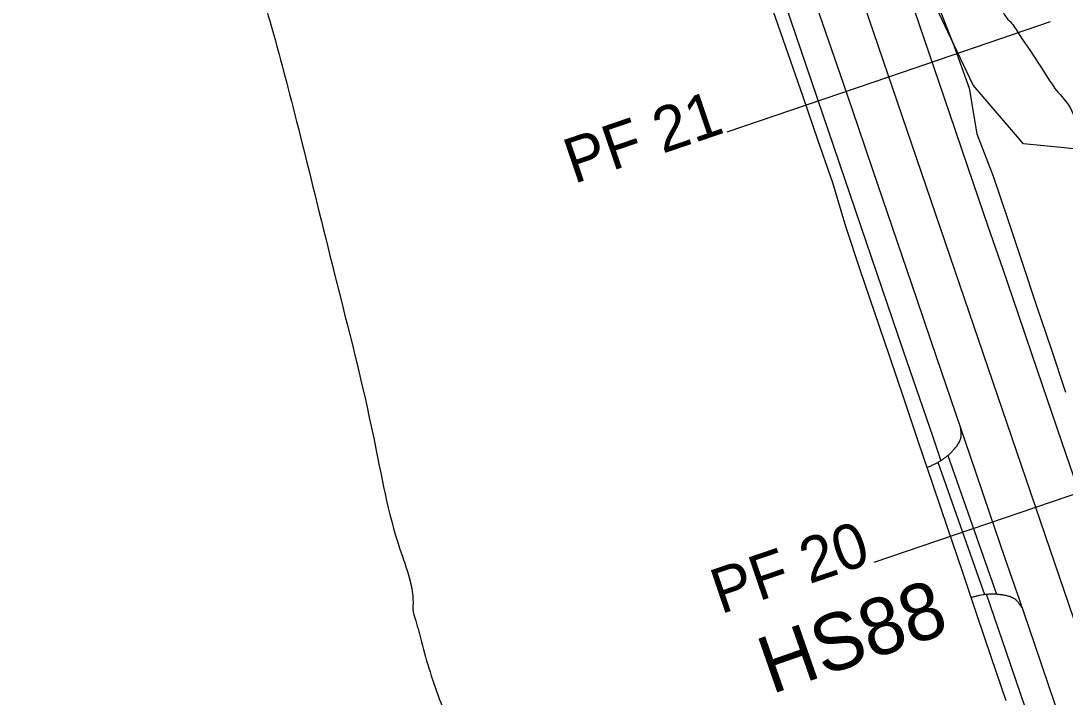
# Model space of a CAD drawing. Extents: x -478102 to -473059, y -1117705 to -1114104.
# Drawn here: x -476532.03 to -476486.18, y -1116879.78 to -1116850.07 of the extents above; entities that cross this region are included whole.
import ezdxf

# ---------------------------------------------------------------- set-up
doc = ezdxf.new("R2010")
doc.units = 0
for name, color, linetype in [('cesty', 7, 'Continuous'), ('POLYGONY_SITUACE_PF', 7, 'Continuous'), ('POLYGONY_SITUACE_PF_POPISY', 7, 'Continuous'), ('POLYGONY_SITUACE_PO', 7, 'Continuous'), ('popis', 7, 'Continuous'), ('RozhraniKultur', 7, 'Continuous'), ('TP_HS', 7, 'Continuous'), ('Vrstevnice_hlavni', 7, 'Continuous'), ('Vrstevnice_vedlejsi', 7, 'Continuous')]:
    doc.layers.add(name, color=color, linetype=linetype)

msp = doc.modelspace()

# ---------------------------------------------------------------- linework, layer by layer
at = {"layer": 'cesty'}
for p, q in [((-476498.334, -1116851.512), (-476498.997, -1116849.625)), ((-476498.334, -1116851.512), (-476498.997, -1116849.625)), ((-476497.785, -1116851.325), (-476498.43, -1116849.432)), ((-476492.79, -1116849.622), (-476491.499, -1116853.408)), ((-476497.68, -1116853.402), (-476498.334, -1116851.512)), ((-476497.68, -1116853.402), (-476498.334, -1116851.512)), ((-476495.849, -1116857.004), (-476497.785, -1116851.325)), ((-476497.031, -1116855.294), (-476497.68, -1116853.402)), ((-476497.031, -1116855.294), (-476497.68, -1116853.402)), ((-476491.499, -1116853.408), (-476490.208, -1116857.194)), ((-476496.382, -1116857.185), (-476497.031, -1116855.294)), ((-476496.382, -1116857.185), (-476497.031, -1116855.294)), ((-476493.268, -1116864.576), (-476495.849, -1116857.004)), ((-476495.805, -1116859.102), (-476496.382, -1116857.185)), ((-476495.805, -1116859.102), (-476496.382, -1116857.185)), ((-476490.208, -1116857.194), (-476489.563, -1116859.087)), ((-476495.173, -1116860.999), (-476495.805, -1116859.102)), ((-476495.173, -1116860.999), (-476495.805, -1116859.102)), ((-476489.563, -1116859.087), (-476488.918, -1116860.98)), ((-476494.532, -1116862.894), (-476495.173, -1116860.999)), ((-476494.532, -1116862.894), (-476495.173, -1116860.999)), ((-476488.918, -1116860.98), (-476488.272, -1116862.873)), ((-476493.891, -1116864.788), (-476494.532, -1116862.894)), ((-476493.891, -1116864.788), (-476494.532, -1116862.894)), ((-476488.272, -1116862.873), (-476487.627, -1116864.766)), ((-476493.251, -1116866.683), (-476493.891, -1116864.788)), ((-476493.251, -1116866.683), (-476493.891, -1116864.788)), ((-476491.977, -1116868.362), (-476493.268, -1116864.576)), ((-476487.627, -1116864.766), (-476486.982, -1116866.659)), ((-476486.982, -1116866.659), (-476486.336, -1116868.552)), ((-476492.61, -1116868.578), (-476493.251, -1116866.683)), ((-476492.61, -1116868.578), (-476493.251, -1116866.683)), ((-476491.636, -1116869.363), (-476491.977, -1116868.362)), ((-476491.969, -1116870.472), (-476492.61, -1116868.578)), ((-476491.969, -1116870.472), (-476492.61, -1116868.578)), ((-476486.336, -1116868.552), (-476485.046, -1116872.338)), ((-476491.328, -1116872.367), (-476491.969, -1116870.472)), ((-476491.328, -1116872.367), (-476491.969, -1116870.472)), ((-476490.687, -1116874.261), (-476491.328, -1116872.367)), ((-476490.687, -1116874.261), (-476491.328, -1116872.367)), ((-476490.046, -1116876.156), (-476490.687, -1116874.261)), ((-476490.046, -1116876.156), (-476490.687, -1116874.261)), ((-476488.751, -1116877.827), (-476489.625, -1116875.262)), ((-476489.406, -1116878.05), (-476490.046, -1116876.156)), ((-476489.406, -1116878.05), (-476490.046, -1116876.156)), ((-476488.765, -1116879.945), (-476489.406, -1116878.05)), ((-476488.765, -1116879.945), (-476489.406, -1116878.05)), ((-476487.46, -1116881.613), (-476488.751, -1116877.827))]:
    msp.add_line(p, q, dxfattribs=at)
for points in [[(-476497.221, -1116849.019), (-476495.93, -1116852.805)], [(-476491.797, -1116849.283), (-476491.061, -1116851.145)], [(-476491.061, -1116851.145), (-476490.394, -1116853.031)], [(-476495.93, -1116852.805), (-476495.285, -1116854.698)], [(-476490.394, -1116853.031), (-476490.058, -1116855.029)], [(-476495.285, -1116854.698), (-476494.64, -1116856.591)], [(-476490.058, -1116855.029), (-476489.332, -1116856.895)], [(-476494.64, -1116856.591), (-476493.994, -1116858.484)], [(-476489.332, -1116856.895), (-476488.696, -1116858.791)], [(-476493.994, -1116858.484), (-476493.349, -1116860.377)], [(-476488.696, -1116858.791), (-476488.061, -1116860.688)], [(-476493.349, -1116860.377), (-476492.704, -1116862.271)], [(-476488.061, -1116860.688), (-476487.426, -1116862.584)], [(-476492.704, -1116862.271), (-476492.058, -1116864.164)], [(-476487.426, -1116862.584), (-476486.79, -1116864.481)], [(-476492.058, -1116864.164), (-476491.413, -1116866.057)], [(-476486.79, -1116864.481), (-476486.155, -1116866.377)], [(-476491.413, -1116866.057), (-476490.768, -1116867.95)], [(-476490.768, -1116867.95), (-476490.122, -1116869.843)], [(-476490.122, -1116869.843), (-476489.477, -1116871.736)], [(-476489.477, -1116871.736), (-476488.832, -1116873.629)], [(-476488.832, -1116873.629), (-476488.186, -1116875.522)], [(-476488.186, -1116875.522), (-476487.541, -1116877.415)], [(-476487.541, -1116877.415), (-476486.896, -1116879.308)], [(-476486.896, -1116879.308), (-476486.25, -1116881.201)]]:
    msp.add_lwpolyline(points, dxfattribs=at)
at = {"layer": 'POLYGONY_SITUACE_PF'}
for points in [[(-476501.013, -1116854.94), (-476493.915, -1116852.52), (-476486.816, -1116850.1)], [(-476494.567, -1116873.851), (-476487.468, -1116871.431), (-476480.369, -1116869.011)]]:
    msp.add_lwpolyline(points, dxfattribs=at)
at = {"layer": 'POLYGONY_SITUACE_PO'}
msp.add_lwpolyline([(-476301.427, -1117045.065), (-476372.905, -1117052.019), (-476378.974, -1117051.908), (-476382.069, -1117051.436), (-476384.865, -1117050.444), (-476390.281, -1117047.7), (-476394.946, -1117043.817), (-476398.626, -1117038.989), (-476458.957, -1116938.029), (-476465.394, -1116926.586), (-476471.221, -1116914.82), (-476476.422, -1116902.765), (-476480.983, -1116890.454), (-476499.392, -1116836.452), (-476499.929, -1116834.228), (-476500.052, -1116831.944), (-476499.756, -1116829.676), (-476499.052, -1116827.5), (-476496.647, -1116821.88)], dxfattribs=at)
at = {"layer": 'RozhraniKultur'}
for p, q in [((-476488.011, -1116855.464), (-476490.21, -1116852.89)), ((-476485.323, -1116855.734), (-476488.011, -1116855.464))]:
    msp.add_line(p, q, dxfattribs=at)
msp.add_lwpolyline([(-476490.21, -1116852.89), (-476505.97, -1116819.69), (-476509.41, -1116806.69), (-476507.1, -1116784.61)], dxfattribs=at)
at = {"layer": 'TP_HS'}
for p, q in [((-476491.334, -1116869.169), (-476489.188, -1116875.25)), ((-476491.761, -1116869.463), (-476489.713, -1116875.267))]:
    msp.add_line(p, q, dxfattribs=at)
for points in [[(-476492.218, -1116869.684), (-476492.13, -1116869.645), (-476491.99, -1116869.579), (-476491.85, -1116869.51), (-476491.737, -1116869.45), (-476491.628, -1116869.383), (-476491.522, -1116869.312), (-476491.47, -1116869.274), (-476491.418, -1116869.236), (-476491.29, -1116869.131), (-476491.172, -1116869.018), (-476491.06, -1116868.897), (-476491.006, -1116868.834), (-476490.952, -1116868.769), (-476490.896, -1116868.696), (-476490.846, -1116868.62), (-476490.804, -1116868.539), (-476490.786, -1116868.497), (-476490.771, -1116868.452), (-476490.752, -1116868.384), (-476490.746, -1116868.349), (-476490.741, -1116868.314), (-476490.737, -1116868.245), (-476490.74, -1116868.176), (-476490.768, -1116867.95)], [(-476490.307, -1116875.396), (-476490.223, -1116875.374), (-476490.072, -1116875.337), (-476489.997, -1116875.32), (-476489.921, -1116875.303), (-476489.795, -1116875.279), (-476489.668, -1116875.262), (-476489.541, -1116875.251), (-476489.477, -1116875.248), (-476489.412, -1116875.245), (-476489.246, -1116875.247), (-476489.083, -1116875.26), (-476488.921, -1116875.284), (-476488.839, -1116875.299), (-476488.756, -1116875.316), (-476488.666, -1116875.338), (-476488.58, -1116875.366), (-476488.497, -1116875.402), (-476488.456, -1116875.424), (-476488.416, -1116875.449), (-476488.359, -1116875.49), (-476488.332, -1116875.513), (-476488.306, -1116875.537), (-476488.282, -1116875.562), (-476488.26, -1116875.588), (-476488.219, -1116875.644), (-476488.099, -1116875.838)]]:
    msp.add_spline(points, degree=3, dxfattribs=at)
at = {"layer": 'Vrstevnice_hlavni'}
msp.add_spline([(-476493.715, -1116836.779), (-476493.657, -1116837.782), (-476493.454, -1116838.814), (-476493.106, -1116839.874), (-476492.613, -1116840.964), (-476491.914, -1116842.563), (-476491.008, -1116844.672), (-476489.895, -1116847.291), (-476489.121, -1116849.068), (-476488.687, -1116850.006), (-476488.591, -1116850.102), (-476488.194, -1116850.666), (-476487.494, -1116851.699), (-476486.491, -1116853.199), (-476485.812, -1116854.196), (-476485.456, -1116854.691), (-476485.422, -1116854.683), (-476485.307, -1116854.78), (-476485.109, -1116854.984), (-476484.829, -1116855.293), (-476484.118, -1116857.163), (-476482.975, -1116860.594), (-476481.402, -1116865.585), (-476480.12, -1116869.665), (-476479.13, -1116872.833), (-476478.431, -1116875.088), (-476477.86, -1116876.887), (-476477.416, -1116878.229), (-476477.099, -1116879.115), (-476476.855, -1116880.078), (-476476.685, -1116881.12), (-476476.587, -1116882.239), (-476476.21, -1116884.112), (-476475.555, -1116886.737), (-476474.62, -1116890.115), (-476473.657, -1116893.01), (-476472.666, -1116895.422), (-476471.647, -1116897.352), (-476470.243, -1116900.412), (-476468.455, -1116904.603), (-476466.283, -1116909.925), (-476464.77, -1116913.634), (-476463.916, -1116915.731), (-476463.721, -1116916.214), (-476463.617, -1116916.722), (-476463.603, -1116917.256), (-476463.679, -1116917.815), (-476463.509, -1116918.911), (-476463.093, -1116920.547), (-476462.43, -1116922.72), (-476462.028, -1116926.548), (-476461.886, -1116932.03), (-476462.123, -1116946.304)], degree=3, dxfattribs=at)
at = {"layer": 'Vrstevnice_vedlejsi'}
msp.add_spline([(-476571.958, -1116704.162), (-476571.904, -1116704.215), (-476571.688, -1116704.429), (-476571.311, -1116704.803), (-476570.773, -1116705.338), (-476569.946, -1116706.363), (-476568.83, -1116707.879), (-476567.427, -1116709.886), (-476566.203, -1116711.628), (-476565.16, -1116713.105), (-476564.298, -1116714.317), (-476563.772, -1116715.225), (-476563.581, -1116715.829), (-476563.726, -1116716.129), (-476564.073, -1116716.669), (-476564.621, -1116717.45), (-476565.371, -1116718.471), (-476565.697, -1116719.715), (-476565.599, -1116721.18), (-476565.077, -1116722.867), (-476563.322, -1116725.926), (-476560.334, -1116730.356), (-476556.114, -1116736.158), (-476552.562, -1116741.631), (-476549.677, -1116746.776), (-476547.46, -1116751.593), (-476545.693, -1116756.042), (-476544.374, -1116760.122), (-476543.504, -1116763.833), (-476542.206, -1116769.314), (-476540.482, -1116776.566), (-476538.329, -1116785.587), (-476536.736, -1116792.746), (-476535.702, -1116798.044), (-476535.228, -1116801.481), (-476533.66, -1116807.541), (-476530.999, -1116816.224), (-476527.246, -1116827.53), (-476524.726, -1116835.32), (-476523.44, -1116839.595), (-476523.389, -1116840.354), (-476523.331, -1116841.083), (-476523.266, -1116841.783), (-476523.195, -1116842.453), (-476522.8, -1116844.094), (-476522.082, -1116846.705), (-476521.041, -1116850.288), (-476519.77, -1116855.097), (-476518.27, -1116861.134), (-476516.539, -1116868.399), (-476515.387, -1116873.283), (-476514.813, -1116875.785), (-476514.818, -1116875.907), (-476514.695, -1116876.43), (-476514.444, -1116877.353), (-476514.064, -1116878.676), (-476513.598, -1116880.016), (-476513.045, -1116881.373), (-476512.404, -1116882.746), (-476510.965, -1116886.684), (-476508.726, -1116893.188), (-476505.69, -1116902.257), (-476503.32, -1116909.062), (-476501.617, -1116913.604), (-476500.581, -1116915.881), (-476499.982, -1116918.695), (-476499.82, -1116922.044), (-476500.095, -1116925.93), (-476500.622, -1116930.955), (-476501.399, -1116937.119), (-476502.428, -1116944.424), (-476503.284, -1116951.043), (-476503.968, -1116956.977), (-476504.479, -1116962.226), (-476505.481, -1116968.833), (-476506.974, -1116976.798), (-476508.959, -1116986.121), (-476510.49, -1116993.241), (-476511.568, -1116998.159), (-476512.192, -1117000.873), (-476513.406, -1117005.693), (-476515.21, -1117012.619), (-476517.605, -1117021.651), (-476519.543, -1117028.708), (-476521.025, -1117033.789), (-476522.05, -1117036.895), (-476522.813, -1117039.387), (-476523.316, -1117041.266), (-476523.557, -1117042.532), (-476525.061, -1117047.398), (-476527.83, -1117055.865), (-476531.861, -1117067.933), (-476534.429, -1117077.623), (-476535.532, -1117084.937), (-476535.172, -1117089.874), (-476535.368, -1117095.964), (-476536.121, -1117103.207)], degree=3, dxfattribs=at)

# ---------------------------------------------------------------- texts
at = {"layer": 'POLYGONY_SITUACE_PF_POPISY'}
for s, p in [('PF 21', (-476507.748, -1116857.236)), ('PF 20', (-476501.301, -1116876.147))]:
    msp.add_text(s, height=1.9765, rotation=18.8241, dxfattribs=at).set_placement(p)
at = {"layer": 'popis'}
msp.add_text('HS88', height=2.5, rotation=19.2622, dxfattribs=at).set_placement((-476499.075, -1116879.664))

doc.saveas('drawing.dxf')
